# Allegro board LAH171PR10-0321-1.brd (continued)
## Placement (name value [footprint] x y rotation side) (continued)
CV622  0.47U_0402_25V6K  [C_0402]  300.17 81.35 180 bottom
CV623  0.47U_0402_25V6K  [C_0402]  282.94 93.8 0 bottom
CV624  0.47U_0402_25V6K  [C_0402]  303.84 89.79 90 bottom
CV625  10U_0402_6.3V6M  [C_0402]  300.67 87.25 90 bottom
CV626  10U_0402_6.3V6M  [C_0402]  297.75 82.45 270 bottom
CV627  10U_0402_6.3V6M  [C_0402]  300.54 90.45 270 bottom
CV628  10U_0402_6.3V6M  [C_0402]  290.43 91.46 90 bottom
CV629  10U_0402_6.3V6M  [C_0402]  298.25 84.07 90 bottom
CV630  0.1U_0402_25V6  [C_0402]  283.98 77.67 180 top
CV632  0.1U_0402_25V6  [C_0402]  134.03 119.9 0 top
CV633  2200P_0402_50V7K  [C_0402]  145.02 125.87 0 top
CV634  0.1U_0402_25V6  [C_0402]  143.81 128.03 0 top
CV635  2200P_0402_50V7K  [C_0402]  137.47 119.91 270 top
CV636  0.1U_0402_25V6  [C_0402]  142.55 131.6 270 top
CV1635  0.1U_0402_25V6K  [C_0402]  118.78 135.42 90 top
CV1637  100P_0402_50V8J  [C_0402]  144.84 134.67 90 top
CV1638  0.1U_0402_25V6K  [C_0402]  110.17 132.04 270 top
CV1641  100P_0402_50V8J  [C_0402]  302.51 84.08 90 bottom
CZ1  0.1U_0201_10V6K  [C_0201]  129.93 130.78 90 top
CZ2  0.1U_0201_10V6K  [C_0201]  125.86 130.27 0 top
CZ3  100P_0402_50V8J  [C_0402]  129.94 133.17 180 top
CZ7  100P_0402_50V8J~D  [C_0402]  274.11 36.46 0 top
CZ8  100P_0402_50V8J~D  [C_0402]  274.11 37.41 0 top
CZ9  100P_0201_25V7K  [C_0201]  271.94 35.32 180 top
CZ10  0.1U_0402_25V6  [C_0402]  270.88 74.99 270 top
CZ11  0.1U_0402_25V6  [C_0402]  271.77 74.99 270 top
CZ12  0.1U_0402_25V6  [C_0402]  281.49 28.32 90 top
CZ13  0.1U_0402_25V6  [C_0402]  282.51 28.32 90 top
CZ17  .047U_0402_16V7K  [C_0402]  262.63 79.32 90 top
CZ18  .047U_0402_16V7K  [C_0402]  277.93 84.4 90 bottom
CZ19  33P_0402_50V8J  [C_0402]  277.04 84.4 90 bottom
CZ20  22U_0603_6.3V6M  [C_0603]  279.01 84.41 90 bottom
CZ21  33P_0402_50V8J  [C_0402]  261.74 79.32 90 top
CZ23  47P_0402_50V8J  [C_0402]  254.76 81.05 270 bottom
CZ24  100P_0402_50V8J  [C_0402]  255.77 81.05 270 bottom
CZ25  2200P_0402_50V7K  [C_0402]  256.79 81.05 270 bottom
CZ26  100U_B2_6.3VM_R35M  [C_B2]  282.25 80.06 90 bottom
CZ27  10U_0603_10V6M  [C_0603]  288.48 38.24 270 top
CZ28  0.01UF_0402_25V7K  [C_0402]  289.62 38.25 270 top
CZ29  0.01UF_0402_25V7K  [C_0402]  271.98 36.66 180 top
CZ30  0.1U_0201_10V6K  [C_0201]  290.38 38.34 270 top
CZ31  0.1U_0201_10V6K  [C_0201]  271.94 35.9 180 top
CZ32  4.7U_0402_10V6M  [C_0402]  271.98 37.55 180 top
CZ33  15P_0402_50V8J  [C_0402]  274.11 35.52 0 top
CZ34  15P_0402_50V8J  [C_0402]  274.11 34.63 0 top
CZ35  15P_0402_50V8J  [C_0402]  274.11 33.74 0 top
CZ36  15P_0402_50V8J  [C_0402]  272.04 34.24 180 top
CZ37  4.7U_0402_6.3V6M  [C_0402]  304.86 10.95 270 top
CZ38  47P_0402_50V8J  [C_0402]  307.21 4.48 270 top
CZ39  33P_0402_50V8J  [C_0402]  308.22 4.48 270 top
CZ40  33P_0402_50V8J  [C_0402]  306.32 4.48 270 top
CZ41  0.1U_0402_25V6  [C_0402]  305.87 10.95 270 top
CZ50  0.1U_0201_10V6K  [C_0201]  248.28 126.91 90 top
CZ51  0.1U_0201_10V6K  [C_0201]  248.28 124.05 90 top
CZ52  10U_0402_6.3V6M  [C_0402]  249.04 124.01 90 top
CZ53  0.1U_0201_10V6K  [C_0201]  239.69 123.8 270 top
CZ54  0.1U_0201_10V6K  [C_0201]  240.32 123.8 270 top
CZ55  10U_0603_10V6M  [C_0603]  238.8 123.76 270 top
CZ56  0.1U_0402_25V6  [C_0402]  238.63 127.66 270 top
CZ57  12P_0402_50V8J  [C_0402]  228.79 39.62 90 top
CZ58  68P_0402_50V8J  [C_0402]  229.74 39.62 90 top
CZ62  100P_0402_50V8J  [C_0402]  232.01 35.7 0 top
CZ63  100P_0402_50V8J  [C_0402]  231.19 37.41 180 top
CZ64  100P_0201_25V7K~D  [C_0201]  228.07 37.51 270 top
CZ66  100P_0201_25V7K~D  [C_0201]  226.56 37.48 270 top
CZ67  100P_0201_25V7K~D  [C_0201]  226.5 40.31 270 top
CZ68  100P_0201_25V7K~D  [C_0201]  228.02 39.72 90 top
CZ69  68P_0402_50V8J  [C_0402]  228.83 37.49 270 top
CZ71  68P_0402_50V8J  [C_0402]  227.3 37.49 270 top
CZ72  68P_0402_50V8J  [C_0402]  227.26 40.21 270 top
CZ73  68P_0402_50V8J  [C_0402]  230.67 39.62 90 top
CZ75  10U_0402_6.3V6M  [C_0402]  249.04 126.87 90 top
CZ80  10P_0402_50V8J  [C_0402]  188.68 35.05 180 top
CZ81  10P_0402_50V8J  [C_0402]  191.13 35.05 0 top
CZ82  0.1U_0201_10V6K  [C_0201]  260.49 57.56 270 top
CZ83  68P_0402_50V8J  [C_0402]  189.81 39.8 90 top
CZ84  68P_0402_50V8J  [C_0402]  183.48 39.5 0 top
CZ85  68P_0402_50V8J  [C_0402]  186.76 39.86 90 top
CZ86  68P_0402_50V8J  [C_0402]  186.63 37.6 270 top
CZ87  68P_0402_50V8J  [C_0402]  187.65 39.86 90 top
CZ88  68P_0402_50V8J  [C_0402]  189.44 37.52 180 top
CZ89  68P_0402_50V8J  [C_0402]  190.3 37.52 0 top
CZ90  100P_0201_25V7K~D  [C_0201]  189.04 39.9 90 top
CZ91  100P_0201_25V7K~D  [C_0201]  186 39.9 90 top
CZ92  100P_0201_25V7K~D  [C_0201]  185.36 39.9 90 top
CZ93  0.1U_0201_10V6K  [C_0201]  284.58 89.23 180 top
CZ100  1U_0201_6.3V6M  [C_0201]  186.85 97.1 180 top
CZ101  0.1U_0402_10V7K  [C_0402]  184.97 102.68 90 top
CZ102  1U_0201_6.3V6M  [C_0201]  124.08 90.18 0 bottom
CZ103  0.1U_0201_10V6K  [C_0201]  126.36 90.85 270 bottom
CZ104  0.1U_0402_10V7K  [C_0402]  120.77 96.39 90 bottom
CZ105  1U_0201_6.3V6M  [C_0201]  186.85 104.91 180 top
CZ106  0.1U_0402_10V7K  [C_0402]  185.15 100.14 90 top
CZ109  470P_0402_50V7K  [C_0402]  258.2 83.46 0 top
CZ110  470P_0402_50V7K  [C_0402]  258.2 82.57 0 top
CZ111  0.1U_0201_10V6K  [C_0201]  256.96 81.24 0 top
CZ112  0.1U_0201_10V6K  [C_0201]  260.88 49.15 270 top
CZ113  470P_0402_50V7K  [C_0402]  260.11 49.02 270 top
CZ114  1000P_0402_50V7K  [C_0402]  259.23 49.02 270 top
CZ115  0.1U_0201_10V6K  [C_0201]  258.46 49.02 270 top
CZ116  0.1U_0201_10V6K  [C_0201]  264.51 41.59 180 top
CZ117  470P_0402_50V7K  [C_0402]  264.89 42.42 180 top
CZ118  470P_0402_50V7K  [C_0402]  264.89 43.33 180 top
CZ119  0.1U_0201_10V6K  [C_0201]  255.77 85.24 180 top
CZ120  0.1U_0201_10V6K  [C_0201]  263.77 33.83 270 top
CZ121  470P_0402_50V7K  [C_0402]  263.79 36.84 180 top
CZ122  0.1U_0201_10V6K  [C_0201]  265.02 44.13 180 top
CZ124  2200P_0402_50V7K  [C_0402]  256 86.07 180 top
CZ129  0.1U_0201_10V6K  [C_0201]  259.93 32.01 0 top
CZ130  470P_0402_50V7K  [C_0402]  258.68 31.19 0 top
CZ150  0.1U_0402_10V7K  [C_0402]  265.17 83.72 270 top
CZ151  0.1U_0402_10V7K  [C_0402]  266.05 83.72 270 top
CZ152  0.22U_0402_10V6K  [C_0402]  271.01 82.9 270 top
CZ153  0.22U_0402_10V6K  [C_0402]  271.9 82.9 270 top
CZ154  .1U_0402_16V7K  [C_0402]  271.77 78.81 90 top
CZ155  .1U_0402_16V7K  [C_0402]  264.4 78.94 90 top
CZ197  470P_0402_50V7K  [C_0402]  268.84 36.52 0 top
CZ198  100P_0402_50V8J  [C_0402]  261.04 84.58 90 bottom
CZ216  0.1U_0201_10V6K  [C_0201]  275.48 67.64 0 top
CZ217  0.1U_0201_10V6K  [C_0201]  273.24 69.57 90 top
CZ218  2.2U_0201_6.3V6M  [C_0201]  264.12 85.51 0 top
CZ305  0.1U_0201_10V6K  [C_0201]  268.36 52.91 90 top
CZ306  470P_0402_50V7K  [C_0402]  266.24 51.48 270 top
CZ309  0.1U_0201_10V6K  [C_0201]  285.43 123.3 270 top
CZ500  0.1U_0402_25V6K  [C_0402]  280.35 120.93 270 top
CZ544  0.1U_0402_25V6  [C_0402]  190.25 92.91 180 top
CZ1200  0.1U_0402_25V6K  [C_0402]  130.68 122.64 180 top
CZ1201  12P_0402_50V8J  [C_0402]  243.14 130.68 90 top
CZ1202  68P_0402_50V8J  [C_0402]  242.18 130.68 90 top
CZ1203  100P_0201_25V7K~D  [C_0201]  190.57 40.73 90 top
CZ1204  100P_0201_25V7K~D  [C_0201]  268.65 45.17 180 top
CZ1205  100P_0201_25V7K~D  [C_0201]  270.35 41.97 0 top
CZ1206  100P_0201_25V7K  [C_0201]  131.85 129.8 0 top
DA1  AZ5123-02S.R7G_SOT23-3  [L03ESDL5V0CC3-2_SOT23-3]  301.96 36.65 270 bottom
DA2  PESD5V0U2BT_SOT23-3  [L03ESDL5V0CC3-2_SOT23-3]  299.91 32.15 270 top
DA3  AZ5123-02S.R7G_SOT23-3  [L03ESDL5V0CC3-2_SOT23-3]  299.89 32.14 90 bottom
DA4  1N4148WS-L_SOD323-2  [1N4148WS-7-F_SOD323-2]  290.58 47.03 0 top
DA5  1N4148WS-L_SOD323-2  [1N4148WS-7-F_SOD323-2]  290.58 45.32 0 top
DA6  PESD5V0U2BT_SOT23-3  [L03ESDL5V0CC3-2_SOT23-3]  292.02 31.92 0 top
DA7  PESD5V0U2BT_SOT23-3  [L03ESDL5V0CC3-2_SOT23-3]  288.08 31.92 0 top
DA8  RB751S40T1G_SOD523-2  [RB520SM-30T2R_EMD2-2]  276.98 61.52 270 top
DA9  -  [AZC199-02SPR7G_SOT23-3]  126.68 126.32 0 top
DA10  -  [AZC199-02SPR7G_SOT23-3]  134.42 127.26 270 top
DD32  PESD5V0V1BDSF SOD962  [ESD8011MUT5G_X3DFN2-2]  119.5 42.75 0 bottom
DE1  BZV55-B5V6_SOD80C2  [BZV55-B5V1_SOD80C2]  95.08 88.92 225 top
DE2  RB751S40T1G_SOD523-2  [RB520SM-30T2R_EMD2-2]  286.66 102.05 180 top
DE43  PESD5V0V1BDSF SOD962  [ESD8011MUT5G_X3DFN2-2]  267.56 100.37 0 bottom
DH1  RB751S40T1G_SOD523-2  [RB520SM-30T2R_EMD2-2]  252.66 114.56 180 top
DH2  RB751S40T1G_SOD523-2  [RB520SM-30T2R_EMD2-2]  250.99 113.29 0 top
DH3  RB751S40T1G_SOD523-2  [RB520SM-30T2R_EMD2-2]  242.1 127.58 0 bottom
DI1  -  [L05ESDL5V0NA-4_SLP2510P8-10-9]  18.86 88.67 270 bottom
DI2  -  [AZC199-02SPR7G_SOT23-3]  24.19 89.99 270 top
DI3  -  [AZC199-02SPR7G_SOT23-3]  297.49 54.47 0 top
DI4  -  [L05ESDL5V0NA-4_SLP2510P8-10-9]  299.07 69.43 90 bottom
DI5  -  [AZC199-02SPR7G_SOT23-3]  295.71 65.48 270 top
DI6  -  [L05ESDL5V0NA-4_SLP2510P8-10-9]  298.68 47.26 90 bottom
DN1  RB751S40T1G_SOD523-2  [RB520SM-30T2R_EMD2-2]  237.69 32.83 270 top
DT1  -  [1N4148WS-7-F_SOD323-2]  60.83 122.75 270 top
DT2  -  [1N4148WS-7-F_SOD323-2]  62.54 123.45 270 top
DT3  -  [1N4148WS-7-F_SOD323-2]  63.18 119.07 270 top
DT4  AZ4A24-01F.R7G_DFN0603P2Y2  [AZ4A24-01FPR7G_DFN0603P2Y2]  19.63 98.69 180 top
DT5  DESD3V3Z1BCSF-7 X2-DSN0603-2  [ESD8011MUT5G_X3DFN2-2]  15.18 103.12 270 bottom
DT6  DESD3V3Z1BCSF-7 X2-DSN0603-2  [ESD8011MUT5G_X3DFN2-2]  15.18 103.84 90 bottom
DT9  DESD3V3Z1BCSF-7 X2-DSN0603-2  [ESD8011MUT5G_X3DFN2-2]  15.88 107.11 90 bottom
DT10  DESD3V3Z1BCSF-7 X2-DSN0603-2  [ESD8011MUT5G_X3DFN2-2]  15.88 106.4 270 bottom
DT13  DESD3V3Z1BCSF-7 X2-DSN0603-2  [ESD8011MUT5G_X3DFN2-2]  15.18 103.12 270 top
DT14  DESD3V3Z1BCSF-7 X2-DSN0603-2  [ESD8011MUT5G_X3DFN2-2]  15.18 103.84 90 top
DT17  DESD3V3Z1BCSF-7 X2-DSN0603-2  [ESD8011MUT5G_X3DFN2-2]  15.88 107.11 90 top
DT18  DESD3V3Z1BCSF-7 X2-DSN0603-2  [ESD8011MUT5G_X3DFN2-2]  15.88 106.4 270 top
DT39  AZ1045-04F_DFN2510P10E-10-9  [L05ESDL5V0NA-4_SLP2510P8-10-9]  22.66 100.22 270 top
DT40  AZ1045-04F_DFN2510P10E-10-9  [L05ESDL5V0NA-4_SLP2510P8-10-9]  22.66 102.22 90 bottom
DT41  AZ1045-04F_DFN2510P10E-10-9  [L05ESDL5V0NA-4_SLP2510P8-10-9]  301.27 115.27 0 top
DT42  AZ1045-04F_DFN2510P10E-10-9  [L05ESDL5V0NA-4_SLP2510P8-10-9]  304.72 115.26 0 top
DV1  -  [BAT54CW_SOT323-3]  138.14 133.17 180 top
DV2  -  [BAT54CW_SOT323-3]  140.93 133.17 180 top
DV3  -  [BAT54CW_SOT323-3]  150.81 135.01 90 top
DV11  RB751S40T1G_SOD523-2  [RB520SM-30T2R_EMD2-2]  144.99 126.95 180 top
DV12  RB751S40T1G_SOD523-2  [RB520SM-30T2R_EMD2-2]  146.9 129.87 180 top
DZ1  RB751S40T1G_SOD523-2  [RB520SM-30T2R_EMD2-2]  284.13 38.17 0 top
DZ2  RB751S40T1G_SOD523-2  [RB520SM-30T2R_EMD2-2]  280.9 38.3 0 top
DZ5  RB751S40T1G_SOD523-2  [RB520SM-30T2R_EMD2-2]  261.04 76.32 90 top
DZ6  RB751S40T1G_SOD523-2  [RB520SM-30T2R_EMD2-2]  263.2 76.32 90 top
DZ8  -  [RB751S40T1G_SOD523-2]  224.79 38.53 90 top
DZ9  -  [BAT54CW_SOT323-3]  276.66 83.07 180 top
DZ10  -  [AZC199-02SPR7G_SOT23-3]  107.12 133.21 180 top
DZ11  -  [AZC199-02SPR7G_SOT23-3]  274.16 121.93 270 top
DZ12  RB751S40T1G_SOD523-2  [RB520SM-30T2R_EMD2-2]  262.69 82.54 90 top
DZ13  -  [L05ESDL5V0NA-4_SLP2510P8-10-9]  306.78 5.49 180 top
FD1  FIDUCIAL MARK~D  [FIDUCIAL_C40M80]  313.01 10.82 0 top
FD2  FIDUCIAL MARK~D  [FIDUCIAL_C40M80]  255.43 22.4 180 bottom
FD3  FIDUCIAL MARK~D  [FIDUCIAL_C40M80]  21.52 111.71 0 top
FD4  FIDUCIAL MARK~D  [FIDUCIAL_C40M80]  9.84 111.64 180 bottom
FV1  1A_65V_T0603FF1000TM  [F_T0603FF1000TM]  124.13 131.52 180 top
FZ1  1A_65V_T0603FF1000TM  [F_T0603FF1000TM]  100.1 132.43 90 bottom
FZ2  1A_65V_T0603FF1000TM  [F_T0603FF1000TM]  134.81 134.81 270 top
FZ3  1A_65V_T0603FF1000TM  [F_T0603FF1000TM]  133.74 124.53 0 top
FZ4  1A_65V_T0603FF1000TM  [F_T0603FF1000TM-NPM]  129.43 128.84 270 top
FZ5  1A_65V_T0603FF1000TM  [F_T0603FF1000TM-NPM]  130.86 129.79 270 top
H1  H_4P0  [H_4P0-G]  119.62 85.52 0 top
H2  -  [H_3P8]  159.52 136 0 top
H3  H_4P0  [H_4P0-G]  183.62 85.52 0 top
H4  H_4P0  [H_4P0-G]  119.62 110.52 0 top
H7  -  [H_3P2]  268.82 120 0 top
H8  -  [H_3P2]  281.95 67.05 0 top
H10  -  [H_3P3]  117.32 129 0 top
H11  H_4P0  [H_4P0-G]  258.53 26.5 0 top
H12  H_4P0  [H_4P0-G]  291.02 120.5 0 top
H13  H_4P0  [H_4P0-G]  183.62 110.52 0 top
H15  -  [H_3P3]  301.52 120 0 top
H16  H_2P6  [H_2P6-G]  69.52 134 0 top
H17  H_2P6  [H_2P6-G]  15.93 112.4 0 top
H18  H_4P0  [H_4P0-G]  301.03 76.5 0 top
H19  -  [H_3P3]  151.72 129 0 top
H20  H_3P0  [H_3P0-G]  315.03 4 0 top
H22  -  [H_2P2N]  80.8 85.85 270 top
H23  H_2P6  [H_2P6-G]  3.02 79.5 0 top
H25  -  [H_4P0N]  77.52 91.2 0 top
H26  -  [H_4P0N]  91.52 30.1 0 top
H27  -  [H_4P0N]  80.52 33 0 top
H30  H_2P6  [H_2P6-G]  249.56 134.02 0 top
H32  -  [H_2P1N]  299.52 43 0 top
H33  H_2P1x3P1N  [H_2P1X3P1N]  8.02 80 90 top
H34  -  [H_5P0N]  159.52 32.35 0 top
H35  H_4P0  [H_4P0-G]  243.52 75 0 top
H36  H_2P5x2P1N  [H_2P5X2P1N]  308.53 20 0 top
H37  -  [H_2P1N]  314.52 20 0 top
JAPS1  CVILU_CF4218FH0R0-05-NH  [CVILU_CF4218FH0R0-05-NH_18P-T]  222.06 32.57 0 top
JDEG1  JXT_FP241AH-010GAAM  [JXT_FP241AH-010GAAM_10P]  262.99 66.08 180 bottom
JDIMM1  LOTES_ADDR0206-P001A  [FOX_ASAA821-H4RB5-7H_260P]  92.87 54.16 180 bottom
JDIMM2  LOTES_ADDR0206-P001A  [FOX_ASAA821-H4RB5-7H_260P]  168.67 51.01 180 bottom
JEDP1  ACES_50398-04041-001  [ACES_50398-04041-001_40P]  124.76 131.08 0 bottom
JESPI  JXT_FP241AH-010GAAM  [JXT_FP241AH-010GAAM_10P]  252.75 79.99 180 bottom
JFAN1  ACES_50271-0040N-001  [ACES_50271-0040N-001_4P]  91.24 91.77 135 bottom
JFPBTN1  FOX_QT510166-L010-7H  [FOX_QT510166-L010-7H_16P]  307.87 116.35 270 bottom
JHDMI1  YUQIU_HD074-F19M1BR-C  [YUQIU_HD074-F19M1BR-C_19P-T]  307.45 89.65 270 bottom
JHP1  SINGA_2SJ3095-136111F~D  [SINGA_2SJ3095-136111F_6P]  306.25 39.35 90 bottom
JIRTS1  ACES_50208-01001-P03  [ACES_50208-01001-P03_10P]  110.23 133.48 180 bottom
JKBTP1  HRS_TF31-20S-0P5SH-800  [HRS_TF31-20S-0P5SH-800_20P-T]  183.51 39.89 0 bottom
JLED1  HRS_TF31-6S-0P5SH  [HRS_TF31-6S-0P5SH_6P-T]  309.07 10.65 180 bottom
JLOM1  SINGA_2RJ3081-1C8211F  [SINGA_2RJ3081-1C8211F_12P-T]  306.2 100.28 90 top
JNGFF1  LOTES_APCI0136-P001A  [LOTES_APCI0136-P001A_75P]  272.7 33.52 0 bottom
JNGFF2  LOTES_APCI0103-P001A  [LOTES_APCI0103-P001A_75P-T]  259.58 74.47 0 bottom
JNGFF3  LOTES_APCI0079-P005A  [LOTES_APCI0079-P005A_75P]  282.82 28.77 180 bottom
JRTC1  ACES_50271-0020N-001  [ACES_50271-0020N-001_2P-S]  298.14 60.74 180 bottom
JSATA1  GS12206-10100-7H  [FOX_GS12206-10100-7H_20P-T]  244.04 38.52 0 bottom
JSD1  T-SOL_158-1240902600  [T-SOL_158-1240902600_23P-T]  304.6 22.86 90 top
JSIM1  JAE_SF51S006V4DR1000Q  [JAE_SF51S006V4DR1000Q_8P-S]  303.28 24.83 270 bottom
JSPI1  ACES_50696-0200M-P01  [ACES_50696-0200M-P01_20P]  242.81 131.03 0 bottom
JSPK1  ACES_50278-00401-001  [ACES_50278-00401-001_4P]  293.82 28.16 180 bottom
JTAG1  @SHORT PADS~D  [SHORTPADS]  276.73 98.5 0 top
JUSB1  C-K_26230A-8K1A-02~D  [C-K_26230A-8K1A-02_9P]  302.93 62.9 270 bottom
JUSB2  C-K_26230A-8K1A-02~D  [C-K_26230A-8K1A-02_9P]  16.12 94.2 90 bottom
JUSB3  C-K_26230A-8K1A-02~D  [C-K_26230A-8K1A-02_9P]  302.93 45.7 270 bottom
JUSBC1  JAE_DX07SD24JJ2R1300~D  [JAE_DX07SD24JJ2R1300_24P]  7.35 109.82 270 top
JUSH1  HRS_TF31C-26S-0P5SH-800  [HRS_TF31C-26S-0P5SH-800_26P-T]  224.28 39.89 0 bottom
JXDP1  JXT_FP270H-061G1AM  [JXT_FP270H-061G1AM_61P]  76.21 134.35 0 bottom
LA5  BLM15PX600SN1D_2P  [MURAT_BLM15PX600SN1D_2P]  293.89 48.33 0 top
LA6  BLM15PD800SN1D_2P  [MURAT_BLM15PD800SN1D_2P]  292.67 35.76 0 top
LA7  BLM15PD800SN1D_2P  [MURAT_BLM15PD800SN1D_2P]  290.45 35.76 0 top
LA8  BLM15PD800SN1D_2P  [MURAT_BLM15PD800SN1D_2P]  288.23 35.76 0 top
LA9  BLM15PD800SN1D_2P  [MURAT_BLM15PD800SN1D_2P]  286.81 36.56 270 top
LA10  BLM15PX330SN1D_2P  [MURAT_BLM15PX330SN1D_2P]  295.55 33.73 0 bottom
LA11  BLM15PX330SN1D_2P  [MURAT_BLM15PX330SN1D_2P]  295.55 30.11 0 bottom
LA12  BLM15PX600SN1D_2P  [MURAT_BLM15PX600SN1D_2P]  280.39 50.89 180 top
LA13  HCB2012KF-121T50_2P  [TAI-T_HCB2012KF-121T50_2P]  285.75 62.8 90 top
LA14  BLM15PX600SN1D_2P  [MURAT_BLM15PX600SN1D_2P]  279.82 58.95 180 top
LA15  BLM15PX330SN1D_2P  [MURAT_BLM15PX330SN1D_2P]  297.07 36.27 0 bottom
LA16  BLM15PX330SN1D_2P  [MURAT_BLM15PX330SN1D_2P]  297.07 38.3 0 bottom
LC1  BLM15GA750SN1D_2P  [MURAT_BLM15GA750SN1D_2P]  221.11 117.71 270 top
LC2  BLM15GA750SN1D_2P  [MURAT_BLM15GA750SN1D_2P]  210.94 84.85 90 bottom
LC3  BLM15GA750SN1D_2P  [MURAT_BLM15GA750SN1D_2P]  217.1 85.93 180 top
LC562  BLM18EG221TN1D_2P~D  [MURAT_BLM18EG221SN1D_2P]  178.91 115.9 0 top
LED3  LTW-C193DC-C_WHITE  [LED_LTW-C193DC-C_2P]  311.88 121.75 180 top
LGA1  -  [LNG2DMTR_LGA12_2X2]  253.76 43.17 270 top
LH421  LQM18PN2R2NC0L_2P~D  [MURAT_BLM18EG221SN1D_2P]  212.88 90.75 180 top
LH423  LQM18PN2R2NC0L_2P~D  [MURAT_BLM18EG221SN1D_2P]  242.47 87.77 0 top
LI3  DLM0NSN900HY2D_4P  [MURAT_DLM0NSN900HY2D_4P]  28.89 89.8 180 top
LI4  DLM0NSN900HY2D_4P  [MURAT_DLM0NSN900HY2D_4P]  297.62 58.92 270 top
LI7  DLM0NSN900HY2D_4P  [MURAT_DLM0NSN900HY2D_4P]  297.5 70.76 0 top
LI8  MCM1012B900F06BP_4P  [INPAQ_MCM1012B900F06BP_4P]  255.21 76.48 0 bottom
LI9  MCM1012B900F06BP_4P  [INPAQ_MCM1012B900F06BP_4P-NPM]  268.43 32.78 0 bottom
LI16  HCM1012GH900BP_4P  [INPAQ_HCM1012GH900BP_4P]  267.32 75.89 270 top
LI17  HCM1012GH900BP_4P  [INPAQ_HCM1012GH900BP_4P]  269.35 75.97 270 top
LI49  BLM15BB100SN1D  [MURAT_BLM15BD121SN1D_2P]  268.63 33.49 0 bottom
LI50  BLM15BB100SN1D  [MURAT_BLM15BD121SN1D_2P]  268.63 32.57 0 bottom
LL1  4.7UH_BRC2012T4R7MD_20%  [TAIYO_BRC2012T4R7MD_2P]  276.85 108.02 270 top
LT1  0.6UH_MND-04ABIR60M-XGL_20%  [MAG_MND-04ABIR60M-XGL_2P]  34.63 112.24 180 bottom
LT2  1UH_LQM18PN1R0MFHD_20%  [MURAT_LQM18NN1R0K00D_2P]  50.23 101.88 90 top
LV1  BLM15PX221SN1D_2P  [MURAT_BLM15PX221SN1D_2P]  136.33 133.82 90 top
LV3  HCM1012GH900BP_4P  [TAIYO_MCF12102G900-T_4P-NPM]  300.92 90.46 0 top
LV6  HCM1012GH900BP_4P  [TAIYO_MCF12102G900-T_4P-NPM]  300.92 88.43 0 top
LV9  HCM1012GH900BP_4P  [TAIYO_MCF12102G900-T_4P-NPM]  300.92 86.4 0 top
LV12  HCM1012GH900BP_4P  [TAIYO_MCF12102G900-T_4P-NPM]  300.92 84.37 0 top
LV601  BLM18KG331SN1D_2P  [MURAT_BLM18KG331SN1D_2P]  300.56 84.02 180 bottom
LV602  BLM18KG331SN1D_2P  [MURAT_BLM18KG331SN1D_2P]  301.81 88.61 270 bottom
LV603  BLM18KG331SN1D_2P  [MURAT_BLM18KG331SN1D_2P]  300.17 82.5 180 bottom
LV604  BLM18KG331SN1D_2P  [MURAT_BLM18KG331SN1D_2P]  302.84 90.62 180 bottom
LV605  BLM18KG331SN1D_2P  [MURAT_BLM18KG331SN1D_2P]  282.49 92.66 0 bottom
LZ1  DLM0NSN900HY2D_4P  [MURAT_DLM0NSN900HY2D_4P]  138.86 127.71 180 top
NOREF  -  []  69.52 134 0 top
NOREF#2  -  []  117.32 129 0 top
NOREF#3  -  []  183.62 110.52 90 top
NOREF#4  -  []  301.03 76.5 270 top
NOREF#5  -  []  291.02 120.5 0 top
NOREF#6  -  []  249.56 134.02 0 top
NOREF#7  -  []  -21.53 236.29 0 top
NOREF#8  -  []  183.62 85.52 90 top
NOREF#9  -  []  151.72 129 0 top
NOREF#10  -  []  268.82 120 0 top
NOREF#11  -  []  128.56 -7.17 0 top
NOREF#12  -  []  15.93 112.4 0 top
NOREF#13  -  []  243.52 75 0 top
NOREF#14  -  []  88.35 40.26 0 top
NOREF#15  -  []  268.82 120 0 top
NOREF#16  -  []  42.03 179.48 0 top
NOREF#17  -  []  258.53 26.5 270 top
NOREF#18  -  []  3.02 79.5 0 top
NOREF#19  -  []  315.03 4 0 top
NOREF#20  -  []  192.65 64.15 0 top
NOREF#21  -  []  119.62 85.52 90 top
NOREF#22  -  []  175.4 59.99 90 top
NOREF#23  -  []  127.88 65.16 0 top
NOREF#24  -  []  147.44 72.2 0 top
NOREF#25  -  []  301.52 120 0 top
NOREF#26  -  []  148.83 64.69 0 top
NOREF#27  -  []  281.95 67.05 0 top
NOREF#28  -  []  119.62 110.52 90 top
NOREF#29  -  []  194.75 76.29 0 top
NOREF#30  -  []  90.18 77.76 180 bottom
NOREF#31  -  []  363.95 148.29 180 bottom
NOREF#32  -  []  141.6 114.75 180 bottom
PBATT1  DEREN_40-42251-01001RHF  [DEREN_40-42251-01001RHF_10P-T]  148.76 42.39 180 bottom
PC1  2200P_0402_50V7K  [C_0402]  148.29 38.91 270 top
PC2  2200P_0402_50V7K  [C_0402]  291.92 62.2 0 bottom
PC3  1U_0402_25V6K  [C_0402]  289.62 68.07 180 bottom
PC4  0.022U_0402_25V7K  [C_0402]  76.51 122.48 180 top
PC5  1000P_0402_50V7K  [C_0402]  69.02 125.54 90 bottom
PC6  0.022U_0402_25V7K  [C_0402]  71.05 125.6 90 bottom
PC7  0.1U_0402_25V6  [C_0402]  70.43 120.98 180 bottom
PC8  10U_0603_25V6M  [C_0603]  72.45 117.93 180 bottom
PC9  12P_0402_50V8J  [C_0402]  290.81 63.1 270 bottom
PC10  4.7U_0402_6.3V6M  [C_0402]  75.37 109.87 180 top
PC11  1000P_0402_50V7K  [C_0402]  78.34 112.08 90 top
PC12  82P_0402_50V8J  [C_0402]  75.37 110.81 90 top
PC13  0.1U_0402_10V7K  [C_0402]  101.79 126.62 90 top
PC100  0.1U_0402_25V6  [C_0402]  248.29 44.21 180 top
PC102  0.1U_0402_25V6  [C_0402]  249.72 50.57 180 bottom
PC103  2200P_0402_50V7K  [C_0402]  248.29 44.21 180 bottom
PC104  10U_0603_25V6M  [C_0603]  248.72 42.11 180 top
PC105  10U_0603_25V6M  [C_0603]  248.72 42.11 180 bottom
PC106  22U_0603_6.3V6M  [C_0603]  244.03 61.92 180 top
PC107  22U_0603_6.3V6M  [C_0603]  244.98 60.65 0 bottom
PC108  22U_0603_6.3V6M  [C_0603]  247.96 60.46 0 bottom
PC109  22U_0603_6.3V6M  [C_0603]  244.03 60.65 180 top
PC110  22U_0603_6.3V6M  [C_0603]  244.03 60.72 180 bottom
PC111  4.7U_0402_6.3V6M  [C_0402]  242.53 47.94 0 bottom
PC112  680P_0402_50V7K  [C_0402]  250.02 49.43 90 top
PC113  1000P_0402_50V7K  [C_0402]  243.26 46.68 270 bottom
PC114  0.1U_0402_25V6  [C_0402]  202.75 35.37 90 top
PC115  0.1U_0402_25V6  [C_0402]  197.87 32.08 180 bottom
PC116  2200P_0402_50V7K  [C_0402]  197.87 32.08 180 top
PC117  10U_0603_25V6M  [C_0603]  197.8 33.22 180 bottom
PC118  10U_0603_25V6M  [C_0603]  197.8 33.22 180 top
PC119  2.2U_0402_6.3V6M  [C_0402]  201.16 39.18 90 bottom
PC120  22U_0603_6.3V6M  [C_0603]  211.78 36.37 0 bottom
PC121  22U_0603_6.3V6M  [C_0603]  211.78 37.58 0 top
PC122  22U_0603_6.3V6M  [C_0603]  211.78 38.79 0 top
PC123  22U_0603_6.3V6M  [C_0603]  211.78 39.99 0 top
PC124  22U_0603_6.3V6M  [C_0603]  211.78 36.37 0 top
PC125  680P_0402_50V7K  [C_0402]  205.66 33.47 0 top
PC126  4.7U_0402_6.3V6M  [C_0402]  200.21 39.18 90 bottom
PC127  1000P_0402_50V7K  [C_0402]  199 39.18 90 bottom
PC128  4.7U_0402_6.3V6M  [C_0402]  198.13 39.19 180 bottom
PC129  22U_0603_6.3V6M  [C_0603]  244.98 61.86 0 top
PC130  22U_0603_6.3V6M  [C_0603]  211.78 39.99 0 bottom
PC135  100P_0402_50V8J  [C_0402]  241.94 59.51 180 top
PC136  27P_0402_50V8J  [C_0402]  245.28 61.73 0 bottom
PC137  100P_0402_50V8J  [C_0402]  202.1 39.14 90 top
PC138  100P_0402_50V8J  [C_0402]  202.1 39.14 90 bottom
PC141  100P_0402_50V8J  [C_0402]  247.19 57.73 0 top
PC142  1U_0402_25V6K  [C_0402]  247.2 58.68 0 top
PC161  22U_0603_6.3V6M  [C_0603]  247.96 61.67 0 bottom
PC162  22U_0603_6.3V6M  [C_0603]  244.98 60.65 0 top
PC163  22U_0603_6.3V6M  [C_0603]  211.78 38.79 0 bottom
PC164  22U_0603_6.3V6M  [C_0603]  211.78 37.58 0 bottom
PC165  100P_0402_50V8J  [C_0402]  200.24 32.15 180 top
PC166  100P_0402_50V8J  [C_0402]  203.34 31.7 0 top
PC167  1U_0402_25V6K  [C_0402]  203.34 32.65 0 top
PC168  1U_0402_25V6K  [C_0402]  200.24 33.11 180 top
PC169  100P_0402_50V8J  [C_0402]  252.17 47.44 180 top
PC170  100P_0402_50V8J  [C_0402]  252.17 48.4 180 top
PC171  1U_0402_25V6K  [C_0402]  252.17 46.49 180 top
PC172  1U_0402_25V6K  [C_0402]  252.18 49.3 180 top
PC200  10U_0603_25V6M  [C_0603]  178.8 36.67 270 top
PC201  10U_0603_25V6M  [C_0603]  178.72 36.67 270 bottom
PC202  82P_0402_50V8J  [C_0402]  179.8 36.69 270 bottom
PC203  0.1U_0402_25V6  [C_0402]  179.88 36.69 270 top
PC204  680P_0402_50V7K  [C_0402]  174.23 36.4 0 top
PC205  0.1U_0402_25V6  [C_0402]  171.08 37.73 180 top
PC206  1U_0201_6.3V6M  [C_0201]  174.23 39.37 90 bottom
PC207  2.2U_0402_6.3V6M  [C_0402]  175 39.43 90 bottom
PC208  330P_0402_50V7K  [C_0402]  175.89 40.35 270 bottom
PC209  22U_0603_6.3V6M  [C_0603]  173.65 33.69 270 bottom
PC210  22U_0603_6.3V6M  [C_0603]  163.32 39.38 270 bottom
PC211  22U_0603_6.3V6M  [C_0603]  163.32 39.38 270 top
PC212  22U_0603_6.3V6M  [C_0603]  162.05 39.38 270 bottom
PC213  22U_0603_6.3V6M  [C_0603]  162.05 39.38 270 top
PC214  10U_0402_6.3V6M  [C_0402]  160.97 39.46 270 bottom
PC216  2200P_0402_50V7K  [C_0402]  160.08 39.46 270 top
PC217  100P_0402_50V8J  [C_0402]  160.08 39.46 270 bottom
PC218  1U_0201_6.3V6M  [C_0201]  176.45 33.79 270 bottom
PC219  22U_0603_6.3V6M  [C_0603]  174.86 33.69 270 bottom
PC221  0.1U_0402_10V7K  [C_0402]  178.99 33.67 0 bottom
PC222  0.1U_0402_10V7K  [C_0402]  178.13 33.67 180 bottom
PC223  10U_0402_6.3V6M  [C_0402]  160.97 39.46 270 top
PC224  100P_0402_50V8J  [C_0402]  159.19 39.46 270 top
PC225  100P_0402_50V8J  [C_0402]  159.19 39.46 270 bottom
PC226  1U_0201_6.3V6M  [C_0201]  173.65 39.37 90 bottom
PC227  1U_0201_6.3V6M  [C_0201]  175.88 33.79 270 bottom
PC228  12P_0402_50V8J  [C_0402]  181.75 36.71 270 top
PC229  12P_0402_50V8J  [C_0402]  179.7 38.16 90 bottom
PC230  12P_0402_50V8J  [C_0402]  175.12 33.72 0 top
PC231  12P_0402_50V8J  [C_0402]  166.3 39.33 270 top
PC232  12P_0402_50V8J  [C_0402]  167.25 39.33 270 top
PC233  2200P_0402_50V7K  [C_0402]  164.4 39.33 270 top
PC234  0.1U_0402_25V6  [C_0402]  165.35 39.33 270 top
PC235  0.1U_0402_25V6  [C_0402]  168.21 39.33 270 top
PC236  100P_0402_50V8J  [C_0402]  180.79 36.71 270 top
PC237  100P_0402_50V8J  [C_0402]  178.75 38.16 90 bottom
PC301  0.1U_0402_25V6  [C_0402]  195.08 82.88 180 bottom
PC302  680P_0402_50V7K  [C_0402]  199.4 88.21 180 top
PC303  100P_0402_50V8J  [C_0402]  195.08 82.88 180 top
PC304  0.1U_0402_25V6  [C_0402]  197.8 82.67 90 bottom
PC305  10U_0603_25V6M  [C_0603]  195.13 83.96 180 bottom
PC306  10U_0603_25V6M  [C_0603]  195.13 83.96 180 top
PC307  330P_0402_50V7K  [C_0402]  197.87 92.02 180 bottom
PC308  22U_0603_6.3V6M  [C_0603]  200.08 91.15 90 bottom
PC309  22U_0603_6.3V6M  [C_0603]  201.35 91.15 90 bottom
PC310  22U_0603_6.3V6M  [C_0603]  200.08 91.15 90 top
PC311  22U_0603_6.3V6M  [C_0603]  201.35 91.15 90 top
PC312  1U_0201_6.3V6M  [C_0201]  197.54 91.11 270 top
PC313  2.2U_0402_6.3V6M  [C_0402]  198.48 89.16 0 top
PC314  1U_0201_6.3V6M  [C_0201]  198.12 91.11 270 top
PC316  100P_0402_50V8J  [C_0402]  197.61 87.72 270 top
PC401  470P_0402_50V7K  [C_0402]  193.72 99.9 0 bottom
PC402  0.1U_0402_25V6  [C_0402]  198.88 94.83 270 top
PC403  10U_0603_25V6M  [C_0603]  200.91 96.66 0 top
PC404  10U_0603_25V6M  [C_0603]  200.91 97.23 0 bottom
PC406  22U_0603_6.3V6M  [C_0603]  192.65 91.7 0 top
PC407  22U_0603_6.3V6M  [C_0603]  192.65 92.91 0 top
PC408  0.1U_0402_25V6  [C_0402]  200.83 98.31 0 bottom
PC409  100P_0402_50V8J  [C_0402]  200.83 97.74 0 top
PC410  100P_0402_50V8J  [C_0402]  200.83 99.51 0 top
PC411  1U_0402_25V6K  [C_0402]  200.83 98.63 0 top
PC425  22U_0603_6.3V6M  [C_0603]  192.65 91.7 0 bottom
PC426  22U_0603_6.3V6M  [C_0603]  192.65 92.91 0 bottom
PC427  0.1U_0402_25V6  [C_0402]  192.64 93.99 0 top
PC428  100P_0402_50V8J  [C_0402]  192.64 94.94 0 top
PC501  22U_0603_6.3V6M  [C_0603]  232.85 76.85 90 top
PC503  68P_0402_50V8J  [C_0402]  232.85 75.84 270 top
PC504  22U_0603_6.3V6M  [C_0603]  234.06 77.42 90 top
PC505  .1U_0402_16V7K  [C_0402]  228.21 73.72 90 top
PC506  680P_0402_50V7K  [C_0402]  228.23 75.64 180 top
PC507  4.7U_0402_6.3V6M  [C_0402]  270.04 66.75 270 bottom
PC508  4.7U_0402_6.3V6M  [C_0402]  270.99 66.75 270 bottom
PC509  0.01UF_0402_25V7K  [C_0402]  269.23 61.85 180 bottom
PC510  0.1U_0402_25V6  [C_0402]  265.72 66.68 270 bottom
PC511  22U_0603_6.3V6M  [C_0603]  270.29 62.48 270 bottom
PC513  .1U_0402_16V7K  [C_0402]  151 34.98 0 top
PC514  4.7U_0402_6.3V6M  [C_0402]  150.14 37.92 180 top
PC515  0.01UF_0402_25V7K  [C_0402]  144.31 34.17 0 top
PC516  22U_0603_6.3V6M  [C_0603]  144.66 36.14 180 top
PC517  4.7U_0402_6.3V6M  [C_0402]  150.14 37.03 180 top
PC530  22U_0603_6.3V6M  [C_0603]  229.42 70.11 90 top
PC531  12P_0402_50V8J  [C_0402]  235.16 77.33 90 top
PC532  12P_0402_50V8J  [C_0402]  236.09 77.32 90 top
PC700  0.1U_0402_25V6  [C_0402]  86.56 37.47 270 top
PC701  2200P_0402_50V7K  [C_0402]  86.56 37.47 270 bottom
PC702  10U_0805_25VAK  [C_0805]  89.04 37.6 270 top
PC703  10U_0805_25VAK  [C_0805]  90.75 37.6 270 top
PC704  10U_0805_25VAK  [C_0805]  92.47 37.6 270 top
PC706  10U_0805_25VAK  [C_0805]  94.18 37.6 270 top
PC707  10U_0603_25V6M  [C_0603]  116.85 33.77 0 top
PC708  10U_0603_25V6M  [C_0603]  116.85 32.56 0 top
PC709  10U_0603_25V6M  [C_0603]  116.85 32.56 0 bottom
PC710  10U_0603_25V6M  [C_0603]  116.85 33.77 0 bottom
PC715  15U_B2_25VM_R100M  [C_B2]  115.3 41.24 180 bottom
PC716  10U_0805_25VAK  [C_0805]  89.04 37.6 270 bottom
PC717  10U_0805_25VAK  [C_0805]  90.75 37.6 270 bottom
PC719  4.7U_0402_6.3V6M  [C_0402]  127.14 40.21 180 bottom
PC720  0.1U_0402_25V6  [C_0402]  116.77 35.87 0 bottom
PC721  2200P_0402_50V7K  [C_0402]  116.77 35.87 0 top
PC725  1U_0402_25V6K  [C_0402]  127.93 41.07 90 bottom
PC726  1U_0402_25V6K  [C_0402]  124.52 41.97 90 bottom
PC727  0.47U_0402_25V6K  [C_0402]  122.36 41.27 90 bottom
PC736  0.1U_0402_25V6  [C_0402]  128.74 36.98 0 bottom
PC737  2.2U_0402_25V6M  [C_0402]  126.74 36.95 90 top
PC738  2.2U_0402_6.3V6M  [C_0402]  121.29 39.06 180 bottom
PC739  2.2U_0402_6.3V6M  [C_0402]  142.35 35.69 180 top
PC740  0.47U_0402_25V6K  [C_0402]  120.72 35.63 180 bottom
PC741  10U_0603_25V6M  [C_0603]  110.55 37.6 270 top
PC742  10U_0603_25V6M  [C_0603]  109.28 37.6 270 top
PC743  4700P_0402_25V7K  [C_0402]  117.01 38.87 0 top
PC744  10P_0402_50V8J  [C_0402]  126.12 32.81 270 top
PC745  0.1U_0402_25V6  [C_0402]  122.04 35.11 90 top
PC746  680P_0402_50V7K  [C_0402]  97.75 35.1 180 top
PC747  680P_0402_50V7K  [C_0402]  108.07 37.55 270 top
PC748  1U_0402_25V6K  [C_0402]  120.4 32.14 180 bottom
PC749  560P_0402_50V7K  [C_0402]  126.17 32.66 270 bottom
PC750  0.1U_0402_25V6  [C_0402]  125.26 32.65 270 bottom
PC751  0.012U_0402_16V7K~D  [C_0402]  127.55 30.36 0 top
PC752  1U_0402_25V6K  [C_0402]  121.28 32.15 270 bottom
PC753  0.22U_0402_25V6K  [C_0402]  120.4 31.19 180 bottom
PC754  0.1U_0402_10V7K  [C_0402]  151.54 32.86 0 top
PC755  0.1U_0402_25V6  [C_0402]  123.54 32.65 270 bottom
PC756  15U_B2_25VM_R100M  [C_B2]  115.3 37.94 180 bottom
PC757  0.1U_0402_25V6  [C_0402]  87.51 37.47 270 top
PC758  10U_0805_25VAK  [C_0805]  94.18 37.6 270 bottom
PC761  2200P_0402_50V7K  [C_0402]  87.51 37.47 270 bottom
PC762  100P_0402_50V8J  [C_0402]  116.77 34.91 0 bottom
PC763  10U_0805_25VAK  [C_0805]  92.47 37.6 270 bottom
PC764  100P_0402_50V8J  [C_0402]  116.77 34.91 0 top
PC765  1U_0402_25V6K  [C_0402]  116.76 36.78 0 top
PC766  1U_0402_25V6K  [C_0402]  117.33 31.49 0 top
PC767  0.1U_0402_25V6  [C_0402]  85.59 37.49 270 top
PC768  100P_0402_50V8J  [C_0402]  84.64 37.49 270 top
PC800  100P_0402_50V8J  [C_0402]  80.07 105.18 270 bottom
PC801  0.01UF_0402_25V7K  [C_0402]  80.32 113.69 270 bottom
PC802  1500P_0402_50V7K  [C_0402]  77.45 122.5 0 top
PC803  0.47U_0402_25V6K  [C_0402]  71.98 123.82 0 top
PC804  220P_0402_50V7K  [C_0402]  78.21 104.9 180 bottom
PC805  1200P_0402_50V7K  [C_0402]  81.08 105.18 270 bottom
PC806  100P_0402_50V8J  [C_0402]  19.88 96.05 180 top
PC807  1000P_0402_50V7K  [C_0402]  19.88 95.16 180 top
PC808  0.1U_0402_25V6  [C_0402]  20.07 91.96 180 top
PC809  100P_0402_50V8J  [C_0402]  20.07 93.74 180 top
PC810  1500P_0402_50V7K  [C_0402]  117.91 74.76 270 top
PC811  10U_0402_6.3V6M  [C_0402]  75.95 111.83 180 bottom
PC812  100P_0402_50V8J  [C_0402]  78.54 112.77 90 bottom
PC813  2.2U_0402_25V6M  [C_0402]  106.75 76.08 180 top
PC814  0.1U_0402_10V7K  [C_0402]  99.55 75.38 0 top
PC815  22U_0603_6.3V6M  [C_0603-S3]  189.16 108.21 270 top
PC816  22U_0603_6.3V6M  [C_0603-S3]  196.78 108.21 270 top
PC817  22U_0603_6.3V6M  [C_0603-S3]  195.51 108.21 270 top
PC818  22U_0603_6.3V6M  [C_0603-S3]  194.24 110.88 90 top
PC834  10U_0402_6.3V6M  [C_0402]  166.88 102.97 180 top
PC835  10U_0402_6.3V6M  [C_0402]  165.91 103.96 180 top
PC836  10U_0402_6.3V6M  [C_0402]  168.05 103.71 0 top
PC837  10U_0402_6.3V6M  [C_0402]  166.98 100.33 270 top
PC838  10U_0402_6.3V6M  [C_0402]  166.88 102.08 180 top
PC839  10U_0402_6.3V6M  [C_0402]  168.82 101.28 90 top
PC840  10U_0402_6.3V6M  [C_0402]  166.88 101.19 180 top
PC841  22U_0603_6.3V6M  [C_0603-S3]  167.59 104.78 0 top
PC842  22U_0603_6.3V6M  [C_0603-S3]  196.78 110.88 90 top
PC843  22U_0603_6.3V6M  [C_0603-S3]  194.24 108.21 270 top
PC844  22U_0603_6.3V6M  [C_0603-S3]  192.97 110.88 90 top
PC848  470U_X_2VM_R6M  [C_X]  111.01 97.1 180 top
PC849  470U_X_2VM_R6M  [C_X]  111.01 92.28 180 top
PC865  0.1U_0402_25V6  [C_0402]  103.81 132.85 0 top
PC1000  22U_0603_6.3V6M  [C_0603-S3]  158.6 100.63 180 top
PC1001  22U_0603_6.3V6M  [C_0603-S3]  163.87 101.29 180 top
PC1002  22U_0603_6.3V6M  [C_0603-S3]  163.19 93.03 180 top
PC1003  22U_0603_6.3V6M  [C_0603-S3]  163.87 102.5 180 top
PC1004  22U_0603_6.3V6M  [C_0603-S3]  164.14 93.04 0 top
PC1005  22U_0603_6.3V6M  [C_0603-S3]  164.31 100.09 0 top
PC1006  22U_0603_6.3V6M  [C_0603-S3]  158.59 97.01 180 top
PC1007  22U_0603_6.3V6M  [C_0603-S3]  163.36 96.47 180 top
PC1008  22U_0603_6.3V6M  [C_0603-S3]  164.31 97.67 0 top
PC1009  22U_0603_6.3V6M  [C_0603-S3]  159.44 93.05 0 top
PC1010  22U_0603_6.3V6M  [C_0603-S3]  141.9 99.7 0 top
PC1011  22U_0603_6.3V6M  [C_0603-S3]  164.31 96.47 0 top
PC1012  22U_0603_6.3V6M  [C_0603-S3]  159.55 97.02 0 top
PC1013  22U_0603_6.3V6M  [C_0603-S3]  158.58 98.22 180 top
PC1014  22U_0603_6.3V6M  [C_0603-S3]  158.6 99.42 180 top
PC1015  22U_0603_6.3V6M  [C_0603-S3]  163.36 98.88 180 top
PC1016  22U_0603_6.3V6M  [C_0603-S3]  164.31 98.88 0 top
PC1017  22U_0603_6.3V6M  [C_0603-S3]  159.55 99.44 0 top
PC1018  22U_0603_6.3V6M  [C_0603-S3]  158.48 93.05 180 top
PC1019  22U_0603_6.3V6M  [C_0603-S3]  159.54 100.65 0 top
PC1020  22U_0603_6.3V6M  [C_0603-S3]  164.95 102.56 270 top
PC1023  10U_0402_6.3V6M  [C_0402]  139.41 97.29 0 top
PC1024  10U_0402_6.3V6M  [C_0402]  145.99 101.96 180 top
PC1025  10U_0402_6.3V6M  [C_0402]  146 102.86 180 top
PC1026  10U_0402_6.3V6M  [C_0402]  139.41 95.39 0 top
PC1027  10U_0402_6.3V6M  [C_0402]  142.1 97.29 180 top
PC1028  10U_0402_6.3V6M  [C_0402]  139.41 96.34 0 top
PC1029  10U_0402_6.3V6M  [C_0402]  139.24 102.78 0 top
PC1030  10U_0402_6.3V6M  [C_0402]  139.23 101.88 0 top
PC1031  1U_0201_6.3V6M  [C_0201]  153.43 103.87 180 top
PC1032  1U_0201_6.3V6M  [C_0201]  155.79 103.87 180 top
PC1033  1U_0201_6.3V6M  [C_0201]  158.15 103.87 180 top
PC1034  1U_0201_6.3V6M  [C_0201]  156.39 104.44 0 top
PC1035  1U_0201_6.3V6M  [C_0201]  158.75 104.44 0 top
PC1036  1U_0201_6.3V6M  [C_0201]  156.93 91.67 0 top
PC1037  1U_0201_6.3V6M  [C_0201]  158.81 91.67 180 top
PC1038  1U_0201_6.3V6M  [C_0201]  149.3 103.87 0 top
PC1039  1U_0201_6.3V6M  [C_0201]  153.43 104.44 180 top
PC1040  1U_0201_6.3V6M  [C_0201]  158.15 104.44 180 top
PC1041  1U_0201_6.3V6M  [C_0201]  150.38 91.74 180 top
PC1042  1U_0201_6.3V6M  [C_0201]  151.37 91.18 0 top
PC1043  1U_0201_6.3V6M  [C_0201]  156.3 92.82 180 top
PC1044  1U_0201_6.3V6M  [C_0201]  156.29 91.58 180 top
PC1045  1U_0201_6.3V6M  [C_0201]  156.29 91.01 180 top
PC1046  1U_0201_6.3V6M  [C_0201]  163.46 103.83 0 top
PC1047  1U_0201_6.3V6M  [C_0201]  161.11 103.87 0 top
PC1048  1U_0201_6.3V6M  [C_0201]  150.38 90.62 180 top
PC1049  1U_0201_6.3V6M  [C_0201]  165.24 91.39 180 top
PC1050  1U_0201_6.3V6M  [C_0201]  168.28 90.81 0 top
PC1051  1U_0201_6.3V6M  [C_0201]  167.65 90.81 180 top
PC1052  1U_0201_6.3V6M  [C_0201]  168.28 91.39 0 top
PC1053  1U_0201_6.3V6M  [C_0201]  163.46 104.39 0 top
PC1054  1U_0201_6.3V6M  [C_0201]  158.75 103.87 0 top
PC1055  1U_0201_6.3V6M  [C_0201]  149.3 104.44 0 top
PC1056  1U_0201_6.3V6M  [C_0201]  151.07 103.87 180 top
PC1057  1U_0201_6.3V6M  [C_0201]  155.79 104.44 180 top
PC1058  1U_0201_6.3V6M  [C_0201]  156.39 103.87 0 top
PC1059  1U_0201_6.3V6M  [C_0201]  151.37 91.74 0 top
PC1060  1U_0201_6.3V6M  [C_0201]  156.3 93.39 180 top
PC1061  1U_0201_6.3V6M  [C_0201]  158.81 91.08 180 top
PC1062  1U_0201_6.3V6M  [C_0201]  156.93 91.11 0 top
PC1063  1U_0201_6.3V6M  [C_0201]  150.38 91.18 180 top
PC1064  1U_0201_6.3V6M  [C_0201]  154.03 103.87 0 top
PC1065  1U_0201_6.3V6M  [C_0201]  151.37 90.62 0 top
PC1066  1U_0201_6.3V6M  [C_0201]  165.24 90.81 180 top
PC1067  1U_0201_6.3V6M  [C_0201]  167.65 91.39 180 top
PC1068  1U_0201_6.3V6M  [C_0201]  161.11 104.44 0 top
PC1069  1U_0201_6.3V6M  [C_0201]  165.86 91.39 0 top
PC1070  1U_0201_6.3V6M  [C_0201]  165.86 90.81 0 top
PC1071  47U_0603_6.3V6M  [C_0603-S3]  158.87 114.75 0 top
PC1072  47U_0603_6.3V6M  [C_0603-S3]  158.87 116.02 0 top
PC1073  47U_0603_6.3V6M  [C_0603-S3]  157.73 114.75 180 top
PC1074  47U_0603_6.3V6M  [C_0603-S3]  153.79 114.75 0 top
PC1075  47U_0603_6.3V6M  [C_0603-S3]  153.79 116.02 0 top
PC1076  47U_0603_6.3V6M  [C_0603-S3]  167.51 114.75 180 top
PC1077  47U_0603_6.3V6M  [C_0603-S3]  157.73 116.02 180 top
PC1079  10U_0402_6.3V6M  [C_0402]  158.1 94.13 180 top
PC1080  10U_0402_6.3V6M  [C_0402]  158.1 95.04 180 top
PC1081  10U_0402_6.3V6M  [C_0402]  162.54 90.75 0 top
PC1082  10U_0402_6.3V6M  [C_0402]  162.93 95.03 180 top
PC1083  10U_0402_6.3V6M  [C_0402]  162.92 94.11 180 top
PC1084  10U_0402_6.3V6M  [C_0402]  159.98 95.04 0 top
PC1085  10U_0402_6.3V6M  [C_0402]  158.9 102.61 0 top
PC1086  10U_0402_6.3V6M  [C_0402]  158.06 101.7 180 top
PC1087  10U_0402_6.3V6M  [C_0402]  160.66 101.7 0 top
PC1088  1U_0201_6.3V6M  [C_0201]  139.76 91.79 180 top
PC1089  1U_0201_6.3V6M  [C_0201]  142.04 102.43 0 top
PC1090  1U_0201_6.3V6M  [C_0201]  147.31 91.94 0 top
PC1091  1U_0201_6.3V6M  [C_0201]  146.11 91.94 180 top
PC1092  1U_0201_6.3V6M  [C_0201]  141.44 102.4 180 top
PC1093  1U_0201_6.3V6M  [C_0201]  141.45 102.98 180 top
PC1094  1U_0201_6.3V6M  [C_0201]  142.04 101.85 0 top
PC1095  1U_0201_6.3V6M  [C_0201]  147.26 102.5 0 top
PC1096  1U_0201_6.3V6M  [C_0201]  142.04 102.99 0 top
PC1097  1U_0201_6.3V6M  [C_0201]  147.26 103.07 0 top
PC1098  1U_0201_6.3V6M  [C_0201]  141.45 101.83 180 top
PC1099  1U_0201_6.3V6M  [C_0201]  139.76 91.23 180 top
PC1171  330U_D2_2.5V_R6M  [C_D2]  184.52 123.37 0 top
PC1629  22U_0603_6.3V6M  [C_0603-S3]  163.36 100.09 180 top
PC1634  22U_0603_6.3V6M  [C_0603-S3]  163.36 97.67 180 top
PC1635  330U_D2_2.5V_R6M  [C_D2]  184.54 118.44 0 top
PC1636  1U_0201_6.3V6M  [C_0201]  160.52 104.44 180 top
PC1637  1U_0201_6.3V6M  [C_0201]  160.52 103.87 180 top
PC1638  1U_0201_6.3V6M  [C_0201]  162.88 104.39 180 top
PC1639  1U_0201_6.3V6M  [C_0201]  162.88 103.83 180 top
PC1640  1U_0201_6.3V6M  [C_0201]  151.66 104.44 0 top
PC1641  1U_0201_6.3V6M  [C_0201]  151.66 103.87 0 top
PC1642  1U_0201_6.3V6M  [C_0201]  154.03 104.44 0 top
PC1643  1U_0201_6.3V6M  [C_0201]  151.07 104.44 180 top
PC1644  10U_0402_6.3V6M  [C_0402]  159.98 94.13 0 top
PC1645  10U_0402_6.3V6M  [C_0402]  167.43 93.77 180 top
PC1646  10U_0402_6.3V6M  [C_0402]  158.9 101.7 0 top
PC1647  10U_0402_6.3V6M  [C_0402]  160.66 102.61 0 top
PC1648  10U_0402_6.3V6M  [C_0402]  151.56 102.61 180 top
PC1649  10U_0402_6.3V6M  [C_0402]  158.1 95.96 180 top
PC1650  10U_0402_6.3V6M  [C_0402]  148.87 102.61 0 top
PC1651  10U_0402_6.3V6M  [C_0402]  158.06 102.61 180 top
PC1652  10U_0402_6.3V6M  [C_0402]  167.45 92.88 180 top
PC1653  10U_0402_6.3V6M  [C_0402]  164.69 94.09 0 top
PC1654  10U_0402_6.3V6M  [C_0402]  164.69 94.99 0 top
PC1675  10U_0402_6.3V6M  [C_0402]  159.98 95.96 0 top
PC2027  10U_0402_6.3V6M  [C_0402]  142.96 97.29 0 top
PC2028  10U_0402_6.3V6M  [C_0402]  140.47 91.37 0 top
PC2029  10U_0402_6.3V6M  [C_0402]  142.96 96.34 0 top
PC2030  22U_0603_6.3V6M  [C_0603-S3]  191.7 110.88 90 top
PC2031  22U_0603_6.3V6M  [C_0603-S3]  142.43 91.51 0 top
PC2032  22U_0603_6.3V6M  [C_0603-S3]  192.97 108.21 270 top
PC2033  22U_0603_6.3V6M  [C_0603-S3]  145.64 100.91 180 top
PC2034  22U_0603_6.3V6M  [C_0603-S3]  143.23 92.94 180 top
PC2035  22U_0603_6.3V6M  [C_0603-S3]  190.43 110.88 90 top
PC2036  22U_0603_6.3V6M  [C_0603-S3]  191.7 108.21 270 top
PC2037  22U_0603_6.3V6M  [C_0603-S3]  139.49 92.93 0 top
PC2038  22U_0603_6.3V6M  [C_0603-S3]  141.9 98.5 0 top
PC2039  22U_0603_6.3V6M  [C_0603-S3]  144.37 92.78 90 top
PC2040  22U_0603_6.3V6M  [C_0603-S3]  139.45 98.37 0 top
PC2041  22U_0603_6.3V6M  [C_0603-S3]  189.16 110.88 90 top
PC2042  22U_0603_6.3V6M  [C_0603-S3]  139.48 100.82 0 top
PC2043  22U_0603_6.3V6M  [C_0603-S3]  138.47 99.01 180 top
PC2044  10U_0402_6.3V6M  [C_0402]  142.96 95.39 0 top
PC2045  22U_0603_6.3V6M  [C_0603-S3]  138.47 100.28 180 top
PC2046  10U_0402_6.3V6M  [C_0402]  143.32 101.96 0 top
PC2047  22U_0603_6.3V6M  [C_0603-S3]  145.64 98.5 180 top
PC2048  22U_0603_6.3V6M  [C_0603-S3]  145.64 99.7 180 top
PC2049  22U_0603_6.3V6M  [C_0603-S3]  195.51 110.88 90 top
PC2050  22U_0603_6.3V6M  [C_0603-S3]  139.49 99.6 0 top
PC2051  22U_0603_6.3V6M  [C_0603-S3]  141.9 100.91 0 top
PC2052  22U_0603_6.3V6M  [C_0603-S3]  139.47 94.14 0 top
PC2053  10U_0402_6.3V6M  [C_0402]  143.34 102.86 0 top
PC2054  22U_0603_6.3V6M  [C_0603-S3]  190.43 108.21 270 top
PC2055  22U_0603_6.3V6M  [C_0603-S3]  138.52 92.9 180 top
PC2056  22U_0603_6.3V6M  [C_0603-S3]  143.23 94.16 180 top
PC2057  10U_0402_6.3V6M  [C_0402]  142.1 95.39 180 top
PC2058  22U_0603_6.3V6M  [C_0603-S3]  138.48 95.6 180 top
PC2060  220U_D7_2VM_R4.5M  [C_D7]  154.37 101.33 270 top
PC2061  220U_D7_2VM_R4.5M  [C_D7]  149.66 100.54 270 top
PC2073  22U_0603_6.3V6M  [C_0603-S3]  163.7 116.02 0 top
PC2074  22U_0603_6.3V6M  [C_0603-S3]  159.55 98.24 0 top
PC2075  22U_0603_6.3V6M  [C_0603-S3]  168.52 114.75 0 top
PC2076  22U_0603_6.3V6M  [C_0603-S3]  162.68 114.75 180 top
PC2077  22U_0603_6.3V6M  [C_0603-S3]  162.68 116.02 180 top
PC2078  22U_0603_6.3V6M  [C_0603-S3]  167.51 116.02 180 top
PC2079  22U_0603_6.3V6M  [C_0603-S3]  163.7 114.75 0 top
PC2080  22U_0603_6.3V6M  [C_0603-S3]  168.52 116.02 0 top
PC2120  22U_0603_6.3V6M  [C_0603-S3]  172.33 114.75 180 top
PC2121  22U_0603_6.3V6M  [C_0603-S3]  172.33 116.02 180 top
PC2208  1U_0201_6.3V6M  [C_0201]  166.51 104.78 180 top
PC2211  .1U_0402_16V7K  [C_0402]  195.15 90.09 90 top
PC2212  470P_0402_50V7K  [C_0402]  198.17 100.76 90 bottom
PC3001  82P_0201_50V8J  [C_0201]  43.37 122.97 90 top
PC3002  0.01UF_0402_25V7K  [C_0402]  42.6 121.56 270 top
PC3003  82P_0201_50V8J  [C_0201]  37.23 123.45 0 top
PC3004  82P_0201_50V8J  [C_0201]  41.18 119.45 180 top
PC3005  0.22U_0402_10V6K  [C_0402]  37.05 121.41 90 top
PC3006  1U_0201_6.3V6M  [C_0201]  44.43 123.77 0 top
PC3007  1U_0201_6.3V6M  [C_0201]  35.8 117.78 180 top
PC3008  1U_0201_6.3V6M  [C_0201]  44.43 123.19 0 top
PC3009  1U_0201_6.3V6M  [C_0201]  45.31 119.82 0 top
PCA1  2200P_0402_50V7K  [C_0402]  203.7 117.63 270 bottom
PCA2  0.1U_0402_25V6  [C_0402]  203.7 117.63 270 top
PCA3  4.7U_0603_25VAK  [C_0603-S3]  202.5 117.68 270 bottom
PCA4  4.7U_0603_25VAK  [C_0603-S3]  202.5 117.68 270 top
PCA7  15U_B2_25VM_R100M  [C_B2]  205.51 114.07 0 bottom
PCA8  4.7U_0402_6.3V6M  [C_0402]  194.62 120.86 270 bottom
PCA9  0.1U_0402_25V6  [C_0402]  200.35 120.85 180 bottom
PCA10  0.47U_0402_25V6K  [C_0402]  200.34 121.82 270 top
PCA11  4.7U_0402_6.3V6M  [C_0402]  194.75 117.29 180 bottom
PCA12  680P_0402_50V7K  [C_0402]  198.64 114.69 180 top
PCA13  100P_0402_50V8J  [C_0402]  201.05 125.36 180 top
PCA14  100P_0402_50V8J  [C_0402]  201.05 124.41 180 top
PCH1  0.1U_0402_25V6  [C_0402]  149.28 124.33 90 bottom
PCH2  1000P_0402_50V7K  [C_0402]  150.24 124.33 90 bottom
PCH3  0.1U_0402_25V6  [C_0402]  165.29 128.83 0 bottom
PCH4  4.7U_0603_25VAK  [C_0603-S3]  184.98 129.21 0 bottom
PCH5  15U_B2_25VM_R100M  [C_B2]  184.88 132.64 180 bottom
PCH6  1000P_0402_50V7K  [C_0402]  149.04 124.33 90 top
PCH7  2200P_0402_50V7K  [C_0402]  165.29 128.83 0 top
PCH8  4.7U_0603_25VAK  [C_0603-S3]  165.36 127.75 0 top
PCH11  0.1U_0402_25V6  [C_0402]  184.97 130.29 0 bottom
PCH13  0.1U_0402_25V6  [C_0402]  148.09 124.33 90 top
PCH14  4.7U_0603_25VAK  [C_0603-S3]  165.36 127.75 0 bottom
PCH15  15U_B2_25VM_R100M  [C_B2]  165.95 132.26 180 bottom
PCH16  2200P_0402_50V7K  [C_0402]  184.97 130.29 0 top
PCH17  4.7U_0603_25VAK  [C_0603-S3]  184.98 129.21 0 top
PCH19  68U_D3L_25VM_R0.07  [C_D3L]  194.23 133.27 0 top
PCH20  0.1U_0402_25V6  [C_0402]  183.02 131.48 90 bottom
PCH21  4.7U_0402_6.3V6M  [C_0402]  179.89 132.01 90 bottom
PCH22  0.47U_0402_25V6K  [C_0402]  182.13 132.4 270 bottom
PCH23  4.7U_0402_6.3V6M  [C_0402]  160.45 130.12 0 top
PCH24  0.1U_0402_25V6  [C_0402]  165.31 129.79 0 bottom
PCH25  0.47U_0402_25V6K  [C_0402]  163.74 130.73 225 top
PCH26  4.7U_0402_6.3V6M  [C_0402]  178.75 127.9 270 top
PCH27  4.7U_0402_6.3V6M  [C_0402]  157.23 127.84 180 bottom
PCH28  680P_0402_50V7K  [C_0402]  179.95 124.33 90 top
PCH29  680P_0402_50V7K  [C_0402]  166.49 123.51 90 top
PCH30  2200P_0402_50V7K  [C_0402]  195.92 131.61 90 bottom
PCH31  0.1U_0402_25V6  [C_0402]  195.89 129.44 270 top
PCH32  4.7U_0603_25VAK  [C_0603-S3]  197.04 129.55 270 top
PCH33  4.7U_0603_25VAK  [C_0603-S3]  194.77 131.66 90 bottom
PCH36  15U_B2_25VM_R100M  [C_B2]  200.78 127.69 90 bottom
PCH37  2200P_0402_50V7K  [C_0402]  175.24 129.49 0 bottom
PCH38  0.1U_0402_25V6  [C_0402]  175.24 129.49 0 top
PCH39  4.7U_0603_25VAK  [C_0603-S3]  175.13 128.34 0 bottom
PCH40  4.7U_0603_25VAK  [C_0603-S3]  175.13 128.34 0 top
PCH43  15U_B2_25VM_R100M  [C_B2]  174.33 132.65 180 bottom
PCH44  4.7U_0402_6.3V6M  [C_0402]  190.56 131.89 90 bottom
PCH45  0.1U_0402_25V6  [C_0402]  193.57 131.65 90 bottom
PCH46  0.47U_0402_25V6K  [C_0402]  192.68 132.55 270 bottom
PCH47  0.1U_0402_25V6  [C_0402]  175.24 130.5 0 bottom
PCH48  4.7U_0402_6.3V6M  [C_0402]  170.22 131.3 90 bottom
PCH49  4.7U_0402_6.3V6M  [C_0402]  187.24 127.75 270 bottom
PCH50  0.47U_0402_25V6K  [C_0402]  172.48 132.33 270 bottom
PCH51  4.7U_0402_6.3V6M  [C_0402]  168.89 127.26 0 top
PCH52  680P_0402_50V7K  [C_0402]  195.07 122.3 90 top
PCH53  680P_0402_50V7K  [C_0402]  170.56 124.2 90 top
PCH54  100P_0402_50V8J  [C_0402]  180.91 129.18 270 top
PCH55  100P_0402_50V8J  [C_0402]  184.02 129.06 270 top
PCT1  68U_D3L_25VM_R0.07  [C_D3L]  93.79 126.34 0 bottom
PCT2  2200P_0402_50V7K  [C_0402]  101.33 91.96 0 top
PCT3  0.1U_0402_25V6  [C_0402]  101.33 92.91 0 bottom
PCT4  4.7U_0603_25VAK  [C_0603-S3]  98.29 89.74 180 bottom
PCT5  4.7U_0603_25VAK  [C_0603-S3]  98.29 91.01 180 bottom
PCT6  4.7U_0603_25VAK  [C_0603-S3]  101.34 90.88 0 bottom
PCT7  4.7U_0603_25VAK  [C_0603-S3]  98.29 89.74 180 top
PCT8  4.7U_0603_25VAK  [C_0603-S3]  101.34 90.88 0 top
PCT9  4.7U_0603_25VAK  [C_0603-S3]  98.29 91.01 180 top
PCT10  0.1U_0402_25V6  [C_0402]  101.33 91.96 0 bottom
PCT11  4.7U_0402_6.3V6M  [C_0402]  97.82 85.51 180 bottom
PCT12  0.47U_0402_25V6K  [C_0402]  97.08 87.71 0 bottom
PCT13  4.7U_0402_6.3V6M  [C_0402]  98.17 84.1 270 bottom
PCT14  680P_0402_50V7K  [C_0402]  105.42 85.1 180 top
PCT15  68U_D3L_25VM_R0.07  [C_D3L]  196.65 129.11 270 bottom
PCT16  100P_0402_50V8J  [C_0402]  101.33 92.89 0 top
PCZ1  2200P_0402_50V7K  [C_0402]  97.09 106.54 0 bottom
PCZ2  0.01UF_0402_25V7K  [C_0402]  97.61 102.93 270 bottom
PCZ3  0.1U_0402_25V6  [C_0402]  94.42 95.3 0 bottom
PCZ4  1000P_0402_50V7K  [C_0402]  96.21 108.27 270 bottom
PCZ5  1000P_0402_50V7K  [C_0402]  96.72 102.93 270 bottom
PCZ6  470P_0402_50V8J  [C_0402]  96.83 101.21 0 top
PCZ7  1000P_0402_50V7K  [C_0402]  98.82 109.03 270 bottom
PCZ8  3300P_0402_25V7K  [C_0402]  97.62 103.81 180 bottom
PCZ9  1000P_0402_50V7K  [C_0402]  96.83 103.94 0 top
PCZ10  0.015U_0402_16V7K  [C_0402]  96.71 105.59 0 bottom
PCZ12  100P_0402_50V8J  [C_0402]  96.71 104.7 0 bottom
PCZ13  1000P_0402_50V7K  [C_0402]  101.29 106.72 90 bottom
PCZ14  2200P_0402_50V7K  [C_0402]  102.18 107.63 270 bottom
PCZ15  1000P_0402_50V7K  [C_0402]  99.45 95.95 270 bottom
PCZ16  2200P_0402_50V7K  [C_0402]  100.4 95.03 90 bottom
PCZ17  47P_0402_50V8J  [C_0402]  104.67 106.67 180 top
PCZ18  470P_0402_50V8J  [C_0402]  102.12 108.46 270 top
PCZ19  470P_0402_50V8J  [C_0402]  97.71 97.74 0 top
PCZ20  2200P_0402_50V7K  [C_0402]  103.83 108.46 270 top
PCZ21  47P_0402_50V8J  [C_0402]  99.5 96.86 270 top
PCZ22  470P_0402_50V8J  [C_0402]  101.23 107.57 270 top
PCZ23  2200P_0402_50V7K  [C_0402]  97.71 95.96 0 top
PCZ24  470P_0402_50V8J  [C_0402]  102.12 95.95 270 bottom
PCZ25  100P_0402_50V8J  [C_0402]  105.56 107.62 180 bottom
PCZ26  820PF_0402_50V7K  [C_0402]  105.56 106.73 180 bottom
PCZ27  0.1U_0402_25V6  [C_0402]  106.44 106.74 270 bottom
PCZ28  82P_0402_50V8J  [C_0402]  105.56 95.94 180 bottom
PCZ29  820PF_0402_50V7K  [C_0402]  105.56 94.98 180 bottom
PCZ30  0.1U_0402_25V6  [C_0402]  106.44 95.95 270 bottom
PCZ31  0.01U_0402_25V7K  [C_0402]  109.28 104.06 0 bottom
PCZ32  0.1U_0402_25V6  [C_0402]  109.28 104.95 0 bottom
PCZ33  0.1U_0402_25V6  [C_0402]  109.47 99.3 0 bottom
PCZ34  4.7U_0402_6.3V6M  [C_0402]  109.47 102.29 0 bottom
PCZ35  0.1U_0402_25V6  [C_0402]  108.09 106.74 270 bottom
PCZ36  0.1U_0402_25V6  [C_0402]  108.23 95.05 180 bottom
PCZ37  0.22U_0402_25V6K  [C_0402]  109.74 106.74 270 bottom
PCZ38  0.47U_0402_25V6K  [C_0402]  111.39 106.74 270 bottom
PCZ39  0.47U_0402_25V6K  [C_0402]  109.47 97.59 0 bottom
PD1  -  [TVNST52302AB0_SOT523-3]  134.25 37.14 90 top
PD2  -  [TVNST52302AB0_SOT523-3]  134.25 35.04 90 top
PD3  BAS40CW_SOT323-3  [DB3J315E0L_SMINI3-F2-B3]  291.59 66.56 180 bottom
PD4  AZ5125-02S.R7G_SOT23-3  [PESD5V0U2BT_SOT23-3]  53.53 122.22 0 top
PD5  S SCH DIO 5A 100V 15UA 0.88V TO227-3  [PDS5100H-13_POWERDI5-3]  79.31 116.91 180 bottom
PD700  SDMK0340L-7-F_SOD323-2~D  [SDMK0340L-7-F_SOD323-2]  128.13 41.54 180 top
PD701  -  [SMF4L22A_SOD123FL2]  83.69 40.83 270 bottom
PD702  SDMK0340L-7-F_SOD323-2~D  [SDMK0340L-7-F_SOD323-2]  127.62 39.82 180 top
PD704  -  [RB520SM-30T2R_EMD2-2]  127.21 43 180 top
PD705  -  [BAT54CW_SOT323-3]  148.29 31.04 270 top
PD706  -  [RB520SM-30T2R_EMD2-2]  129.92 41.56 270 top
PD800  -  [BAT54CW_SOT323-3]  82.16 112.72 180 bottom
PD801  S SCH DIO 5A 100V 15UA 0.88V TO227-3  [PDS5100H-13_POWERDI5-3]  81.21 121.63 90 top
PD802  -  [SDMK0340L-7-F_SOD323-2]  75.43 110.24 270 bottom
PD803  -  [BAT54CW_SOT323-3]  81.31 111.49 180 top
PD3000  -  [BAT54CW_SOT323-3]  38.03 118.75 0 top
PD3001  -  [RB520SM-30T2R_EMD2-2]  39.6 124.62 0 top
PD3002  -  [RB520SM-30T2R_EMD2-2]  35.17 121.13 270 top
PHZ1  100K_0402_1%_TSM0B104F4251RZ  [R_0402]  192.79 112.93 180 bottom
PHZ2  220K_0402_5%_ERTJ0EV224J  [R_0402]  149.22 119.7 90 bottom
PHZ3  220K_0402_5%_ERTJ0EV224J  [R_0402]  109.16 89.8 180 bottom
PHZ4  220K_0402_5%_ERTJ0EV224J  [R_0402]  157.23 126.95 180 bottom
PHZ5  220K_0402_5%_ERTJ0EV224J  [R_0402]  103.88 82.89 270 top
